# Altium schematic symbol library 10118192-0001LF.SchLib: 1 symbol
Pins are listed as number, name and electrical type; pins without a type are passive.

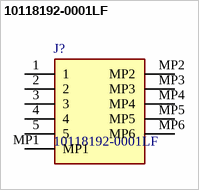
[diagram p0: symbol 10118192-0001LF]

## 10118192-0001LF
designator J?
Micro USB, Input Output Connectors, B TYPE RECEPTACLE with flange; Manufacturer_Name: Amphenol Communications Solutions; Geometry.Height: 3.05mm
footprint 101181920001LF
pins: 1, 2, 3, 4, 5, MP1, MP2, MP3, MP4, MP5, MP6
